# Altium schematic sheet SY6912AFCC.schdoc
size 127 x 101 mm
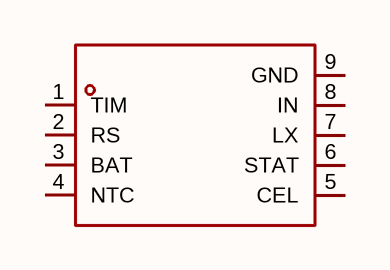
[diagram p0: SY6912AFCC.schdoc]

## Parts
U?  sy6912afcc  [SO-8_L4.9-W3.9-P1.27-LS6.0-BL-EP]  (value not drawn)

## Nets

Not connected (* = marked no-connect by the designer): U? 1(TIM) 2(RS) 3(BAT) 4(NTC) 5(CEL) 6(STAT) 7(LX) 8(IN) 9(GND)

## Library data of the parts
U? = sy6912afcc: 功能类型:降压型;工作电压:4V~23V;输出电压:4.2V；12.6V；8.4V;输出电流:2A;输出类型:固定;; Manufacturer: Silergy(矽力杰); AddInBom: yes; ModelId: 756fba4e187a48c69a2c935cd5c4465b; ModelName: SO-8_L4.9-W3.9-H1.5-LS5.9-P1.27; ModelTransform: 240.39054,192.913,0,270,0,0,0.004,-0.002,0; Function: 降压型; Voltage - Supply: 4V~23V; Output Current: 2A; Frequency - Switching: 800kHz; Synchronous Rectifier: 是; Number of Outputs: 1; Topology: 降压式; Switch tube (built-in/external): 内置; Output Type: 固定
